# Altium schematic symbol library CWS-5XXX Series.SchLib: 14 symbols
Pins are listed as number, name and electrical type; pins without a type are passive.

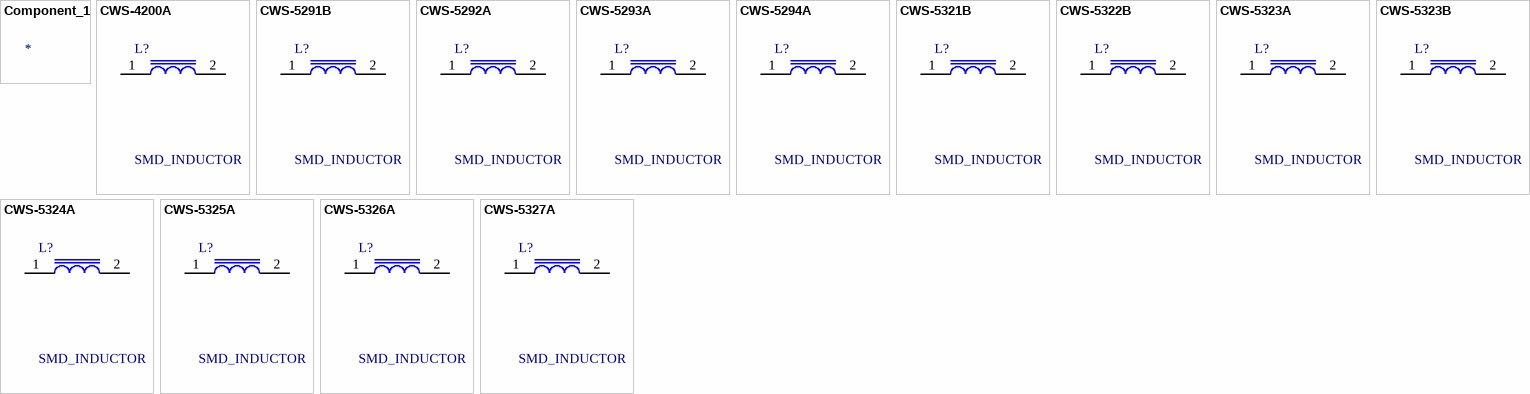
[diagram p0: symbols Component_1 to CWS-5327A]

## Component_1
designator *  (value not drawn)

## CWS-4200A
designator L?, comment SMD_INDUCTOR
POWER INDUCTOR 25 A, 0.65 uH, 3.50 milli ohms, 7.87 mm (L), 7.87 mm (W), 6.1 mm (H); Manufacturer #1: CWS; Sim.Analog.Order: Model$; Current: 25 A; DCR: 3.50 mOhms; Inductance: 0.65 uH
footprint CWS-4200A
pins: 1, 2

## CWS-5291B
designator L?, comment SMD_INDUCTOR
POWER INDUCTOR 60 A, 0.30 uH, 0.55 milli ohms, 13.21 mm (L), 14.22 mm (W), 5.33 mm (H); Manufacturer #1: CWS; Sim.Analog.Order: Model$; Current: 60 A; DCR: 0.55 mOhms; Inductance: 0.30 uH
footprint CWS-5291B
pins: 1, 2

## CWS-5292A
designator L?, comment SMD_INDUCTOR
POWER INDUCTOR 80 A, 0.25 uH, 0.40 milli ohms, 13.97 mm (L), 17.78 mm (W), 5.69 mm (H); Manufacturer #1: CWS; Sim.Analog.Order: Model$; Current: 80 A; DCR: 0.40 mOhms; Inductance: 0.25 uH
footprint CWS-5292A
pins: 1, 2

## CWS-5293A
designator L?, comment SMD_INDUCTOR
POWER INDUCTOR 60 A, 0.65 uH, 0.70 milli ohms, 13.97 mm (L), 19.05 mm (W), 5.84 mm (H); Manufacturer #1: CWS; Sim.Analog.Order: Model$; Current: 60 A; DCR: 0.70 mOhms; Inductance: 0.65 uH
footprint CWS-5293A
pins: 1, 2

## CWS-5294A
designator L?, comment SMD_INDUCTOR
POWER INDUCTOR 50 A, 1.20 uH, 1.10 milli ohms, 13.97 mm (L), 17.27 mm (W), 5.84 mm (H); Manufacturer #1: CWS; Sim.Analog.Order: Model$; Current: 50 A; DCR: 1.10 mOhms; Inductance: 1.20 uH
footprint CWS-5294A
pins: 1, 2

## CWS-5321B
designator L?, comment SMD_INDUCTOR
POWER INDUCTOR 40 A, 2.00 uH, 2.10 milli ohms, 13.21 mm (L), 13.72 mm (W), 5.33 mm (H); Manufacturer #1: CWS; Sim.Analog.Order: Model$; Current: 40 A; DCR: 2.10 mOhms; Inductance: 2.00 uH
footprint CWS-5321B
pins: 1, 2

## CWS-5322B
designator L?, comment SMD_INDUCTOR
POWER INDUCTOR 50 A, 0.70 uH, 0.90 milli ohms, 13.21 mm (L), 13.97 mm (W), 5.33 mm (H); Manufacturer #1: CWS; Sim.Analog.Order: Model$; Current: 50 A; DCR: 0.90 mOhms; Inductance: 0.70 uH
footprint CWS-5322B
pins: 1, 2

## CWS-5323A
designator L?, comment SMD_INDUCTOR
POWER INDUCTOR 40 A, 1.30 uH, 1.80 milli ohms, 13.72 mm (L), 10.67 mm (W), 5.59 mm (H); Manufacturer #1: CWS; Sim.Analog.Order: Model$; Current: 40 A; DCR: 1.80 mOhms; Inductance: 1.30 uH
footprint CWS-5323B
pins: 1, 2

## CWS-5323B
designator L?, comment SMD_INDUCTOR
POWER INDUCTOR 40 A, 1.30 uH, 1.80 milli ohms, 13.72 mm (L), 10.67 mm (W), 5.59 mm (H); Manufacturer #1: CWS; Sim.Analog.Order: Model$; Current: 40 A; DCR: 1.80 mOhms; Inductance: 1.30 uH
footprint CWS-5323B
pins: 1, 2

## CWS-5324A
designator L?, comment SMD_INDUCTOR
POWER INDUCTOR 21 A, 2.70 uH, 4.20 milli ohms, 13.72 mm (L), 10.67 mm (W), 5.59 mm (H); Manufacturer #1: CWS; Sim.Analog.Order: Model$; Current: 21 A; DCR: 4.20 mOhms; Inductance: 2.70 uH
footprint CWS-5324A
pins: 1, 2

## CWS-5325A
designator L?, comment SMD_INDUCTOR
POWER INDUCTOR 21 A, 3.90 uH, 4.90 milli ohms, 13.72 mm (L), 10.67 mm (W), 5.59 mm (H); Manufacturer #1: CWS; Sim.Analog.Order: Model$; Current: 21 A; DCR: 4.90 mOhms; Inductance: 3.90 uH
footprint CWS-5325A 
pins: 1, 2

## CWS-5326A
designator L?, comment SMD_INDUCTOR
POWER INDUCTOR 17 A, 4.70 uH, 7.00 milli ohms, 13.72 mm (L), 10.67 mm (W), 5.59 mm (H); Manufacturer #1: CWS; Sim.Analog.Order: Model$; Current: 17 A; DCR: 7.00 mOhms; Inductance: 4.70 uH
footprint CWS-5326A 
pins: 1, 2

## CWS-5327A
designator L?, comment SMD_INDUCTOR
POWER INDUCTOR 12 A, 7.60 uH, 14.00 milli ohms, 13.72 mm (L), 11.94 mm (W), 5.59 mm (H); Manufacturer #1: CWS; Sim.Analog.Order: Model$; Current: 12 A; DCR: 14.00 mOhms; Inductance: 7.60 uH
footprint CWS-5327A 
pins: 1, 2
